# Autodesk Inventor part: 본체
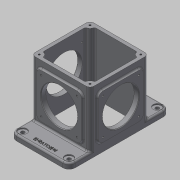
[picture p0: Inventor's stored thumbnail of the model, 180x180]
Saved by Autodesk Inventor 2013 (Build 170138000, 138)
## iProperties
Created: 2018-09
Part Number: 본체
Material: 일반
Document SubType Name: Modeling
Designer: mduedu
Density: 1 g/cm^3
Author: mduedu
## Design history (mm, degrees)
sketch "스케치1"
  geometry: L1 (90, 52.5)-(-90, 52.5); L2 (-90, 52.5)-(-90, -52.5); L3 (-90, -52.5)-(90, -52.5); L4 (90, -52.5)-(90, 52.5); L5 (90, 52.5)-(-90, -52.5); L6 (-90, 52.5)-(90, -52.5); 1 further point
  constraints: 12 end point, 2 midpoint, 2 parallel, 1 horizontal, 1 perpendicular
  dimensions: "d0" = 180 distance of L3.end L2.end; "d1" = 105 distance of L2.end L1.end
extrude "돌출1" new body sketch "스케치1" distance "d2" = 10; taper "d3" = 0 deg
sketch "스케치2"
  geometry: L1 (-52.5, -52.5)-(52.5, -52.5); L2 (52.5, -52.5)-(52.5, 52.5); L3 (52.5, 52.5)-(-52.5, 52.5); L4 (-52.5, 52.5)-(-52.5, -52.5); L5 (-52.5, -52.5)-(52.5, 52.5); L6 (52.5, -52.5)-(-52.5, 52.5); 1 further point
  constraints: 12 end point, 2 midpoint, 2 parallel, 1 horizontal, 1 perpendicular
  dimensions: "d4" = 105 distance of L3.end L2.end; "d5" = 105 distance of L2.end L1.end
extrude "돌출2" join sketch "스케치2" distance "d6" = 100; taper "d7" = 0 deg
sketch "스케치14"
  geometry: L1 (-52.5, 52.5)-(52.5, 52.5) reference; L2 (52.5, 52.5)-(52.5, -52.5) reference; L3 (52.5, -52.5)-(-52.5, -52.5) reference; L4 (-52.5, -52.5)-(-52.5, 52.5) reference; L5 (46.5, 46.5)-(-46.5, 46.5); L6 (-46.5, 46.5)-(-46.5, -46.5); L7 (-46.5, -46.5)-(46.5, -46.5); L8 (46.5, -46.5)-(46.5, 46.5); 1 further point
  constraints: 8 end point, 3 other
  dimensions: "d85" = 6 distance between parallel lines of L5 L1
extrude "돌출10" cut sketch "스케치14" stored distance "d86" = 10; taper "d87" = 0 deg
fillet "모깎기1" dims "d12" = 7
sketch "스케치15"
  geometry: A1 r 7 centre (-45.5, 45.5) between (-45.5, 52.5) and (-52.5, 45.5) reference; A2 r 7 centre (45.5, 45.5) between (52.5, 45.5) and (45.5, 52.5) reference; A3 r 7 centre (45.5, -45.5) between (45.5, -52.5) and (52.5, -45.5) reference; A4 r 7 centre (-45.5, -45.5) between (-52.5, -45.5) and (-45.5, -52.5) reference; 5 further points
  constraints: 4 coincident, 4 vertical alignment, 8 other
extrude "돌출11" join sketch "스케치15" stored distance "d88" = 10; taper "d89" = 0 deg
fillet "모깎기15" dims "d90" = 3
sketch "스케치6"
  geometry: L1 (50, 17.5)-(130, 17.5); L2 (130, 17.5)-(130, 97.5); L3 (130, 97.5)-(50, 97.5); L4 (50, 97.5)-(50, 17.5); L5 (50, 17.5)-(130, 97.5); L6 (130, 17.5)-(50, 97.5); L7 (0, 0)-(180, 0) reference; 4 further points
  constraints: 12 end point, 4 midpoint, 2 parallel, 1 horizontal, 1 perpendicular, 1 vertical alignment
  dimensions: "d25" = 80 distance of L3.end L2.end; "d26" = 80 distance of L2.end L1.end; "d27" = 57.5 distance of point (90, 0) point (90, 57.5)
extrude "돌출6" join sketch "스케치6" distance "d28" = 3; taper "d29" = 0 deg
fillet "모깎기7" dims "d30" = 8
sketch "스케치7"
  geometry: C1 r 32.5 at (90, 57.5); 1 further point
  constraints: 1 centre point, 1 vertical alignment
  dimensions: "d32" = 65 diameter of C1; "d33" = 57.5 distance of C1.centre point (90, 0)
extrude "돌출7" cut sketch "스케치7" stored distance "d34" = 3; taper "d35" = 0 deg
fillet "모깎기9" dims "d36" = 3
sketch "스케치8"
  geometry: L1 (5.5, 7.5)-(85.5, 7.5); L2 (85.5, 7.5)-(85.5, 87.5); L3 (85.5, 87.5)-(5.5, 87.5); L4 (5.5, 87.5)-(5.5, 7.5); L5 (5.5, 7.5)-(85.5, 87.5); L6 (85.5, 7.5)-(5.5, 87.5); L7 (-7, -10)-(98, -10) reference; C1 r 32.5 at (45.5, 47.5); 4 further points
  constraints: 12 end point, 4 midpoint, 2 parallel, 1 centre point, 1 coincident, 1 horizontal, 1 perpendicular, 1 vertical alignment
  dimensions: "d37" = 80 distance of L3.end L2.end; "d38" = 80 distance of L2.end L1.end; "d39" = 57.5 distance from line of point (45.5, 47.5) L7; "d40" = 65 diameter of C1
extrude "돌출8" join sketch "스케치8" distance "d41" = 3; taper "d42" = 0 deg
fillet "모깎기10" dims "d43" = 8
extrude "돌출9" cut sketch "스케치8" stored distance "d44" = 3; taper "d45" = 0 deg
fillet "모깎기11" dims "d46" = 3
sketch "스케치9"
  geometry: L1 (50, 89.5)-(50, 25.5) reference; L2 (58, 17.5)-(122, 17.5) reference; L3 (130, 25.5)-(130, 89.5) reference; L4 (122, 97.5)-(58, 97.5) reference; C1 r 32.5 at (90, 57.5) reference; A1 r 8 centre (58, 89.5) between (58, 97.5) and (50, 89.5) reference; A2 r 8 centre (58, 25.5) between (50, 25.5) and (58, 17.5) reference; A3 r 8 centre (122, 25.5) between (122, 17.5) and (130, 25.5) reference; A4 r 8 centre (122, 89.5) between (130, 89.5) and (122, 97.5) reference; 5 further points
  constraints: 4 coincident
hole "구멍1" sketch "스케치9" at (58, 89.5), (122, 89.5), (122, 25.5), (58, 25.5) diameter "d47" = 3.242; stored, may be unused: countersink angle "d51" = 90 deg, drill point angle "d53" = 118 deg; dims "d48" = 6, "d49" = 4, "d50" = 2, "d52" = 9
sketch "스케치10" dims "d30" = 8
  geometry: L1 (13.5, 7.5)-(77.5, 7.5) reference; L2 (85.5, 15.5)-(85.5, 79.5) reference; L3 (77.5, 87.5)-(13.5, 87.5) reference; L4 (5.5, 79.5)-(5.5, 15.5) reference; C1 r 32.5 at (45.5, 47.5) reference; A1 r 8 centre (13.5, 15.5) between (5.5, 15.5) and (13.5, 7.5) reference; A2 r 8 centre (77.5, 15.5) between (77.5, 7.5) and (85.5, 15.5) reference; A3 r 8 centre (77.5, 79.5) between (85.5, 79.5) and (77.5, 87.5) reference; A4 r 8 centre (13.5, 79.5) between (13.5, 87.5) and (5.5, 79.5) reference; 5 further points
  constraints: 4 coincident
hole "구멍2" sketch "스케치10" at (13.5, 79.5), (77.5, 79.5), (77.5, 15.5), (13.5, 15.5) diameter "d54" = 3.242; stored, may be unused: countersink angle "d58" = 90 deg, drill point angle "d60" = 118 deg; dims "d30" = 8, "d55" = 6, "d56" = 4, "d57" = 2, "d59" = 9
fillet "모깎기12" dims "d68" = 11
sketch "스케치16"
  geometry: A1 r 11 centre (-79, 41.5) between (-79, 52.5) and (-90, 41.5) reference; A2 r 11 centre (-79, -41.5) between (-90, -41.5) and (-79, -52.5) reference; A3 r 11 centre (79, 41.5) between (90, 41.5) and (79, 52.5) reference; A4 r 11 centre (79, -41.5) between (79, -52.5) and (90, -41.5) reference; 5 further points
  constraints: 4 coincident
hole "구멍5" sketch "스케치16" at (-79, 41.5), (79, 41.5), (79, -41.5), (-79, -41.5) diameter "d91" = 6.6; stored, may be unused: countersink angle "d95" = 90 deg, drill point angle "d97" = 118 deg; dims "d92" = 6, "d93" = 15, "d94" = 2, "d96" = 8
fillet "모깎기13" dims "d77" = 3
fillet "모깎기14" dims "d78" = 3
chamfer "모따기1" distance "d79" = 1; stored, may be unused: second distance "d80" = 2, angle "d81" = 45 deg
sketch "스케치17"
  geometry: A1 r 7 centre (-45.5, 45.5) between (-45.5, 52.5) and (-52.5, 45.5) reference; A2 r 7 centre (-45.5, -45.5) between (-52.5, -45.5) and (-45.5, -52.5) reference; A3 r 7 centre (45.5, -45.5) between (45.5, -52.5) and (52.5, -45.5) reference; A4 r 7 centre (45.5, 45.5) between (52.5, 45.5) and (45.5, 52.5) reference; 5 further points
  constraints: 4 coincident
hole "구멍6" sketch "스케치17" at (-45.5, 45.5), (45.5, 45.5), (45.5, -45.5), (-45.5, -45.5) diameter "d98" = 3.242; stored, may be unused: countersink angle "d102" = 90 deg, drill point angle "d104" = 118 deg; dims "d99" = 8, "d100" = 15, "d101" = 2, "d103" = 10
sketch "스케치13"
  geometry: L1 (90, -41.5)-(90, 41.5) reference; 2 further points
  constraints: 1 horizontal alignment, 1 other
  dimensions: "d82" = 10 distance from line of point (80, 0) L1
feature "엠보싱1" sketch "스케치13" dims "d0" = 180, "d1" = 105, "d25" = 80, "d26" = 80, "d27" = 57.5, "d83" = 0.5, "d84" = 0
node "솔리드1"
mirror "대칭1"
mirror "대칭2"
node "투영된 루프2"
node "투영된 루프3"
node "투영된 루프6"
